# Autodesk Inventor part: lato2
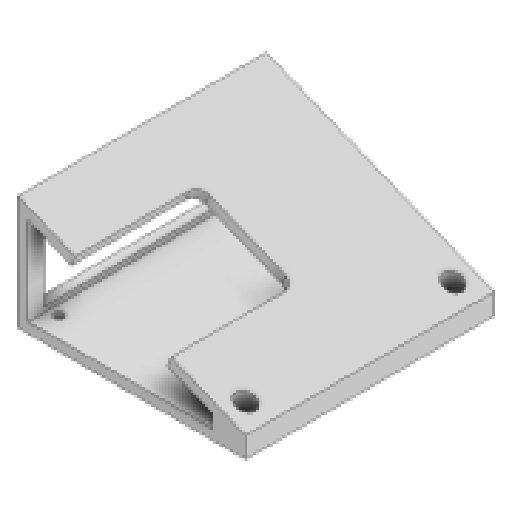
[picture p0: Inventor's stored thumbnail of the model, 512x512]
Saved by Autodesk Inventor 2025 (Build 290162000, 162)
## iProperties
Created: 2025-05
Part Number: lato2
Material: Plastica PET
Document SubType Name: Modeling
Designer: R5800u
Density: 1.541 g/cm^3
Appearance: Acciaio - Lucido
Author: R5800u
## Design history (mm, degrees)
sketch "Schizzo1"
  geometry: L1 (0, 0)-(190, 0) reference; L2 (190, 0)-(190, 5) reference; L3 (0, 5)-(190, 5) reference; L4 (0, 0)-(0, 5) reference; L5 (300, -50)-(300, -55) reference; L6 (300, -50)-(300, -40); L7 (300, -40)-(190, 5); L8 (190, 5)-(190, -50); L9 (190, -50)-(300, -50); L10 (195, -2.448)-(295, -43.357); L11 (295, -43.357)-(295, -45); L12 (295, -45)-(195, -45); L13 (195, -45)-(195, -2.448); L14 (284, -38.857)-(284, -45); 1 further point
  constraints: 18 end point, 3 point on line, 2 perpendicular, 1 vertical, 3 other
  dimensions: "d0" = 10 distance of L5.start L6.end; "d1" = 5 distance between parallel lines of L7 L10; "d2" = 16 distance between parallel lines of L6 L14
extrude "Estrusione1" new body sketch "Schizzo1" distance "d3" = 120; taper "d4" = 0 deg
sketch "Schizzo2"
  geometry: L1 (0, 55)-(0, 0) reference; L2 (0, 55)-(-120, 55) reference; L3 (-120, 0)-(-120, 55) reference; L4 (0, 0)-(-120, 0) reference; L5 (-112.5, 47.5)-(-7.5, 47.5); L6 (-7.5, 47.5)-(-7.5, 7.5); L7 (-7.5, 7.5)-(-112.5, 7.5); L8 (-112.5, 7.5)-(-112.5, 47.5); 1 further point
  constraints: 8 end point, 3 other
  dimensions: "d5" = 7.5 distance between parallel lines of L2 L5
extrude "Estrusione2" cut sketch "Schizzo2" stored distance "d6" = 10; taper "d7" = 0 deg
sketch "Schizzo3"
  geometry: L1 (81.5, -69.5)-(81.5, -61.5) reference; L2 (93.5, -69.5)-(81.5, -69.5) reference; L3 (93.5, -61.5)-(93.5, -69.5) reference; L4 (81.5, -61.5)-(93.5, -61.5) reference; L5 (93.5, 61.5)-(81.5, 61.5) reference; L6 (81.5, 61.5)-(81.5, 69.5) reference; L7 (81.5, 69.5)-(93.5, 69.5) reference; 1 further point
  constraints: 14 end point, 4 horizontal, 3 vertical, 8 other
extrude "Estrusione3" cut sketch "Schizzo3" distance "d8" = 10; taper "d9" = 0 deg
sketch "Schizzo4"
  geometry: L1 (110, -107.9)-(110, -112.1) reference; L2 (110, -110)-(100, -110); L3 (0, -120)-(110, -120) reference; L4 (100, -120)-(100, 0); L5 (0, 0)-(110, 0) reference; L6 (100, -60)-(110, -60); L7 (110, 0)-(110, -120) reference; L8 (100, -10)-(10, -10); L9 (0, 0)-(0, -120) reference; 6 further points
  constraints: 10 end point, 3 midpoint, 3 point on line, 2 coincident, 2 horizontal, 2 symmetric about line, 2 vertical, 2 other
  dimensions: "d10" = 10 distance of L2.start L2.end; "d11" = 10 distance from line of L6 point (100, -70); "d19" = 10 distance from line of L9 L8.end
hole "Foro1" sketch "Schizzo4" at (100, -110), (100, -10), (10, -10), (10, -110) diameter "d12" = 4.5; stored, may be unused: countersink angle "d16" = 90 deg, drill point angle "d18" = 118 deg; dims "d13" = 6, "d14" = 9.4, "d15" = 2, "d17" = 20
node "Piano di lavoro1"
sketch "Schizzo6"
  geometry: C1 r 2.25 at (95, 110) reference; C2 r 2.25 at (95, 10) reference; 1 further point
hole "Foro2" sketch "Schizzo6" at (95, 10), (95, 110) diameter "d21" = 5.5; stored, may be unused: countersink angle "d25" = 90 deg, drill point angle "d27" = 118 deg; dims "d22" = 6, "d23" = 9, "d24" = 8, "d26" = 20
sketch "Schizzo7"
  geometry: L1 (-88.849, -55)-(-88.849, 0) reference; L2 (-28.849, 0)-(-28.849, -55) reference; L3 (-88.849, 0)-(-28.849, 0); L4 (-28.849, 0)-(-28.849, 60); L5 (-28.849, 60)-(-88.849, 60); L6 (-88.849, 60)-(-88.849, 0); 1 further point
  constraints: 8 end point, 2 parallel, 1 horizontal, 1 perpendicular
  dimensions: "d28" = 60 distance of L4.end L3.end; "d32" = 60 distance of L4.end L5.end
extrude "Estrusione4" cut sketch "Schizzo7" distance "d29" = 10; taper "d30" = 0 deg
fillet "Raccordo1" dims "d31" = 5
node "Solido1"
node "Riferimento1"
node "Riferimento2"
node "Linea chiusa proiettata1"
node "Riferimento3"
node "Riferimento4"
other parameters: "d20" = 11
